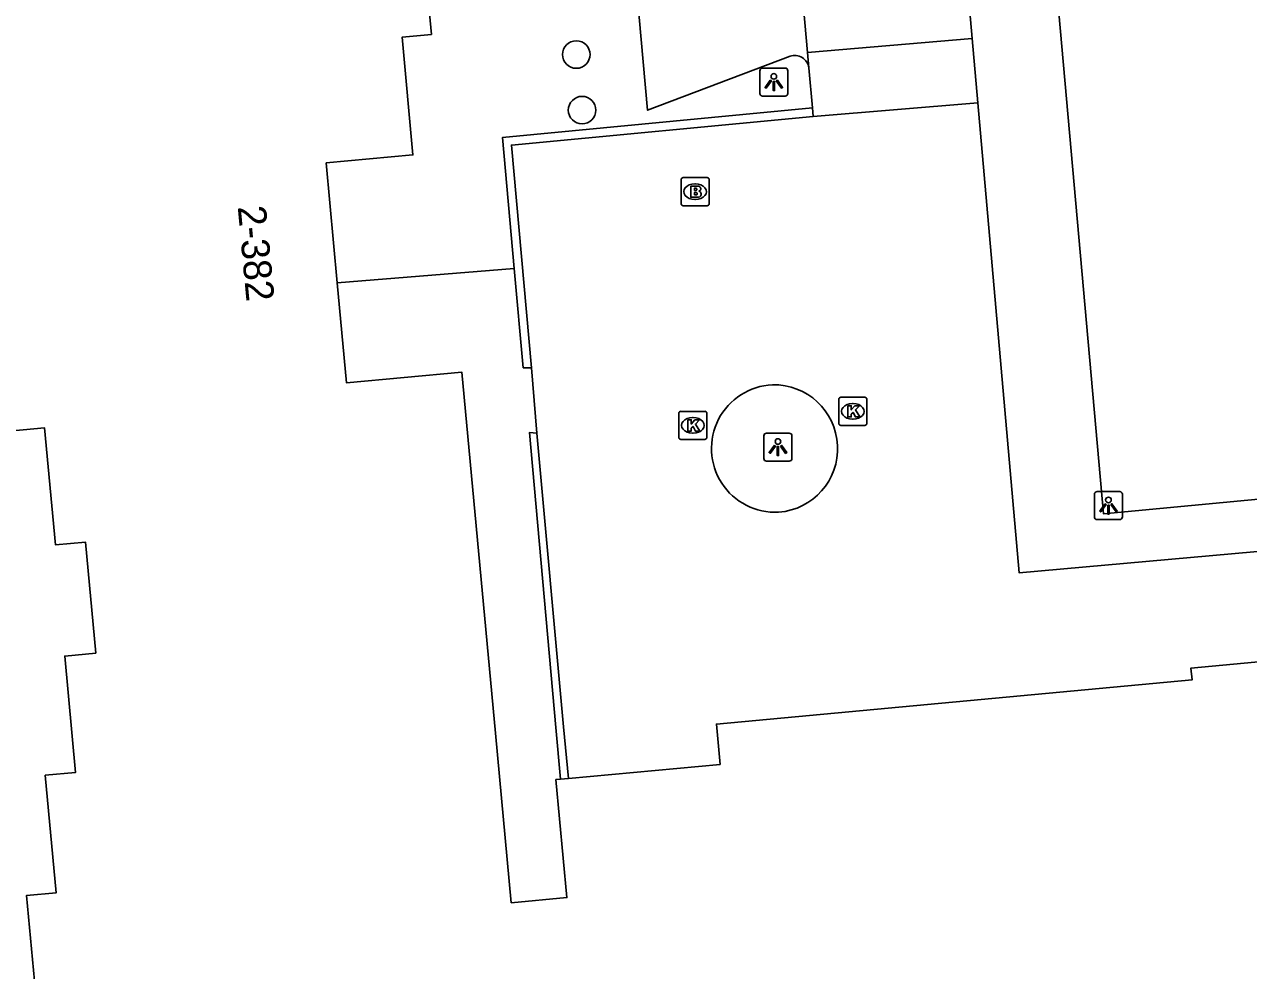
# Model space of a CAD drawing. Extents: x 157793 to 159380, y 380882 to 382313.
# Drawn here: x 158289.2 to 158332.75, y 381192.48 to 381226.15 of the extents above; entities that cross this region are included whole.
import ezdxf

# ---------------------------------------------------------------- set-up
doc = ezdxf.new("R2010")
doc.units = 0
for name, color, linetype in [('IMGEO_Boom', 7, 'Continuous'), ('IMGEO_Brandkraan', 7, 'Continuous'), ('IMGEO_Kolk', 7, 'Continuous'), ('IMGEO_Lichtpunt', 7, 'Continuous'), ('IMGEO_Muur', 7, 'Continuous'), ('IMGEO_Pand', 7, 'Continuous'), ('IMGEO_Pand_nummerreeks', 7, 'Continuous'), ('IMGEO_Parkeervlak_open', 7, 'Continuous'), ('IMGEO_Rijbaan_lokaal_open', 7, 'Continuous'), ('IMGEO_Voetpad_open', 7, 'Continuous')]:
    doc.layers.add(name, color=color, linetype=linetype)

msp = doc.modelspace()

# ---------------------------------------------------------------- linework, layer by layer
at = {"layer": 'IMGEO_Boom'}
for centre in [(158308.835, 381225.082), (158309.039, 381223.104)]:
    msp.add_circle(centre, 0.489, dxfattribs=at)
at = {"layer": 'IMGEO_Brandkraan'}
for p, q in [((158312.561, 381219.776), (158312.561, 381220.628)), ((158312.636, 381220.702), (158313.488, 381220.702)), ((158313.049, 381220.482), (158313.074, 381220.482)), ((158313.562, 381220.628), (158313.562, 381219.776)), ((158313.488, 381219.702), (158312.636, 381219.702)), ((158313.072, 381219.922), (158313.047, 381219.922))]:
    msp.add_line(p, q, dxfattribs=at)
for points in [[(158312.561, 381219.776), (158312.561, 381220.628)], [(158312.636, 381220.702), (158313.488, 381220.702)], [(158312.909, 381220.402), (158312.909, 381220.002), (158313.122, 381220.002)], [(158313.14, 381220.402), (158312.909, 381220.402)], [(158313.562, 381220.628), (158313.562, 381219.776)], [(158313.088, 381220.321), (158313.034, 381220.321), (158313.034, 381220.245)], [(158313.034, 381220.245), (158313.087, 381220.245)], [(158313.096, 381220.169), (158313.034, 381220.169), (158313.034, 381220.088)], [(158313.034, 381220.088), (158313.096, 381220.088)], [(158313.488, 381219.702), (158312.636, 381219.702)]]:
    msp.add_lwpolyline(points, dxfattribs=at)
for centre, radius, start, end in [((158312.638, 381220.626), 0.0765, 91.552, 178.448), ((158312.638, 381220.626), 0.0765, 91.552, 178.448), ((158313.144, 381220.257), 0.145, 59.4692, 91.5367), ((158313.486, 381220.626), 0.0765, 1.552, 88.448), ((158313.486, 381220.626), 0.0765, 1.552, 88.448), ((158313.089, 381220.283), 0.0379, 267.8285, 90.9355), ((158313.097, 381220.128), 0.0404, 269.8759, 90.5077), ((158313.128, 381220.253), 0.251, 268.6676, 293.5347), ((158313.169, 381220.304), 0.0922, 285.5137, 58.1501), ((158313.174, 381220.112), 0.105, 301.3115, 78.989), ((158312.638, 381219.778), 0.0765, 181.552, 268.448), ((158312.638, 381219.778), 0.0765, 181.552, 268.448), ((158313.486, 381219.778), 0.0765, 271.552, 358.448), ((158313.486, 381219.778), 0.0765, 271.552, 358.448)]:
    msp.add_arc(centre, radius, start, end, dxfattribs=at)
for centre, major_axis, ratio, start_param, end_param in [((158313.048, 381220.202), (-0.387, 0.002), 0.722429, 4.712389, 7.853982), ((158313.073, 381220.202), (-0.39, 0.002), 0.717154, 1.570796, 4.712389)]:
    msp.add_ellipse(centre, major_axis=major_axis, ratio=ratio, start_param=start_param, end_param=end_param, dxfattribs=at)
at = {"layer": 'IMGEO_Kolk'}
for p, q in [((158318.173, 381211.956), (158318.173, 381212.808)), ((158318.248, 381212.882), (158319.1, 381212.882)), ((158318.661, 381212.662), (158318.686, 381212.662)), ((158319.174, 381212.808), (158319.174, 381211.956)), ((158312.481, 381211.457), (158312.481, 381212.309)), ((158312.556, 381212.383), (158313.408, 381212.383)), ((158312.969, 381212.163), (158312.994, 381212.163)), ((158313.482, 381212.309), (158313.482, 381211.457)), ((158319.1, 381211.882), (158318.248, 381211.882)), ((158318.684, 381212.102), (158318.659, 381212.102)), ((158313.408, 381211.383), (158312.556, 381211.383)), ((158312.992, 381211.603), (158312.967, 381211.603))]:
    msp.add_line(p, q, dxfattribs=at)
for points in [[(158318.173, 381211.956), (158318.173, 381212.808)], [(158318.248, 381212.882), (158319.1, 381212.882)], [(158318.494, 381212.582), (158318.617, 381212.582), (158318.617, 381212.431), (158318.747, 381212.582), (158318.911, 381212.582), (158318.765, 381212.431), (158318.918, 381212.182), (158318.766, 381212.182), (158318.681, 381212.346), (158318.617, 381212.279), (158318.617, 381212.182), (158318.494, 381212.182), (158318.494, 381212.582)], [(158319.174, 381212.808), (158319.174, 381211.956)], [(158312.481, 381211.457), (158312.481, 381212.309)], [(158312.556, 381212.383), (158313.408, 381212.383)], [(158313.482, 381212.309), (158313.482, 381211.457)], [(158312.802, 381212.083), (158312.925, 381212.083), (158312.925, 381211.932), (158313.055, 381212.083), (158313.219, 381212.083), (158313.073, 381211.932), (158313.226, 381211.683), (158313.074, 381211.683), (158312.989, 381211.847), (158312.925, 381211.78), (158312.925, 381211.683), (158312.802, 381211.683), (158312.802, 381212.083)], [(158319.1, 381211.882), (158318.248, 381211.882)], [(158313.408, 381211.383), (158312.556, 381211.383)]]:
    msp.add_lwpolyline(points, dxfattribs=at)
for centre, start, end in [((158318.25, 381212.806), 91.552, 178.448), ((158318.25, 381212.806), 91.552, 178.448), ((158319.098, 381212.806), 1.552, 88.448), ((158319.098, 381212.806), 1.552, 88.448), ((158312.558, 381212.307), 91.552, 178.448), ((158312.558, 381212.307), 91.552, 178.448), ((158313.406, 381212.307), 1.552, 88.448), ((158313.406, 381212.307), 1.552, 88.448), ((158318.25, 381211.958), 181.552, 268.448), ((158318.25, 381211.958), 181.552, 268.448), ((158319.098, 381211.958), 271.552, 358.448), ((158319.098, 381211.958), 271.552, 358.448), ((158312.558, 381211.459), 181.552, 268.448), ((158312.558, 381211.459), 181.552, 268.448), ((158313.406, 381211.459), 271.552, 358.448), ((158313.406, 381211.459), 271.552, 358.448)]:
    msp.add_arc(centre, 0.0765, start, end, dxfattribs=at)
for centre, major_axis, ratio, start_param, end_param in [((158318.66, 381212.382), (-0.387, 0.002), 0.722429, 4.712389, 7.853982), ((158318.685, 381212.382), (-0.39, 0.002), 0.717154, 1.570796, 4.712389), ((158312.968, 381211.883), (-0.387, 0.002), 0.722429, 4.712389, 7.853982), ((158312.993, 381211.883), (-0.39, 0.002), 0.717154, 1.570796, 4.712389)]:
    msp.add_ellipse(centre, major_axis=major_axis, ratio=ratio, start_param=start_param, end_param=end_param, dxfattribs=at)
at = {"layer": 'IMGEO_Lichtpunt'}
for p, q in [((158315.364, 381224.507), (158315.364, 381223.7)), ((158315.364, 381224.507), (158315.364, 381223.7)), ((158316.266, 381224.602), (158315.458, 381224.602)), ((158316.266, 381224.602), (158315.458, 381224.602)), ((158316.36, 381223.7), (158316.36, 381224.507)), ((158316.36, 381223.7), (158316.36, 381224.507)), ((158315.458, 381223.606), (158316.266, 381223.606)), ((158315.458, 381223.606), (158316.266, 381223.606)), ((158315.509, 381211.513), (158315.509, 381210.706)), ((158315.509, 381211.513), (158315.509, 381210.706)), ((158316.411, 381211.608), (158315.603, 381211.608)), ((158316.411, 381211.608), (158315.603, 381211.608)), ((158316.505, 381210.706), (158316.505, 381211.513)), ((158316.505, 381210.706), (158316.505, 381211.513)), ((158315.603, 381210.612), (158316.411, 381210.612)), ((158315.603, 381210.612), (158316.411, 381210.612)), ((158328.172, 381209.527), (158327.364, 381209.527)), ((158328.172, 381209.527), (158327.364, 381209.527)), ((158327.27, 381209.432), (158327.27, 381208.625)), ((158327.27, 381209.432), (158327.27, 381208.625)), ((158328.266, 381208.625), (158328.266, 381209.432)), ((158328.266, 381208.625), (158328.266, 381209.432)), ((158327.364, 381208.531), (158328.172, 381208.531)), ((158327.364, 381208.531), (158328.172, 381208.531))]:
    msp.add_line(p, q, dxfattribs=at)
for points in [[(158315.738, 381224.171), (158315.777, 381224.143), (158315.589, 381223.881), (158315.551, 381223.908), (158315.738, 381224.171)], [(158315.84, 381224.123), (158315.887, 381224.123), (158315.887, 381223.801), (158315.84, 381223.801), (158315.84, 381224.123)], [(158315.95, 381224.143), (158315.988, 381224.17), (158316.175, 381223.908), (158316.136, 381223.88), (158315.95, 381224.143)], [(158315.883, 381211.177), (158315.922, 381211.149), (158315.734, 381210.887), (158315.696, 381210.914), (158315.883, 381211.177)], [(158315.985, 381211.129), (158316.032, 381211.129), (158316.032, 381210.807), (158315.985, 381210.807), (158315.985, 381211.129)], [(158316.095, 381211.149), (158316.133, 381211.176), (158316.32, 381210.914), (158316.281, 381210.886), (158316.095, 381211.149)], [(158327.644, 381209.096), (158327.683, 381209.068), (158327.495, 381208.806), (158327.457, 381208.833), (158327.644, 381209.096)], [(158327.856, 381209.068), (158327.894, 381209.095), (158328.081, 381208.833), (158328.042, 381208.805), (158327.856, 381209.068)], [(158327.746, 381209.048), (158327.793, 381209.048), (158327.793, 381208.726), (158327.746, 381208.726), (158327.746, 381209.048)]]:
    msp.add_lwpolyline(points, dxfattribs=at)
for centre in [(158315.863, 381224.305), (158316.008, 381211.311), (158327.769, 381209.23)]:
    msp.add_circle(centre, 0.0994, dxfattribs=at)
for centre, start, end in [((158315.458, 381224.507), 90, 180), ((158315.458, 381224.507), 90, 180), ((158316.266, 381224.507), 0, 90), ((158316.266, 381224.507), 0, 90), ((158315.458, 381223.7), 180, 270), ((158315.458, 381223.7), 180, 270), ((158316.266, 381223.7), 270, 0), ((158316.266, 381223.7), 270, 360), ((158315.603, 381211.513), 90, 180), ((158315.603, 381211.513), 90, 180), ((158316.411, 381211.513), 0, 90), ((158316.411, 381211.513), 0, 90), ((158315.603, 381210.706), 180, 270), ((158315.603, 381210.706), 180, 270), ((158316.411, 381210.706), 270, 0), ((158316.411, 381210.706), 270, 360), ((158327.364, 381209.432), 90, 180), ((158327.364, 381209.432), 90, 180), ((158328.172, 381209.432), 0, 90), ((158328.172, 381209.432), 0, 90), ((158327.364, 381208.625), 180, 270), ((158327.364, 381208.625), 180, 270), ((158328.172, 381208.625), 270, 0), ((158328.172, 381208.625), 270, 360)]:
    msp.add_arc(centre, 0.0946, start, end, dxfattribs=at)
at = {"layer": 'IMGEO_Muur'}
for points in [[(158306.627, 381217.472), (158306.209, 381222.134), (158317.24, 381223.185)], [(158317.24, 381223.185), (158317.267, 381222.88)], [(158317.267, 381222.88), (158306.525, 381221.862), (158307.24, 381213.936)], [(158307.24, 381213.936), (158306.944, 381213.934), (158306.627, 381217.472)], [(158308.266, 381199.289), (158308.101, 381201.134), (158307.165, 381211.625), (158307.427, 381211.606)], [(158307.427, 381211.606), (158308.383, 381201.16), (158308.552, 381199.315)]]:
    msp.add_lwpolyline(points, dxfattribs=at)
at = {"layer": 'IMGEO_Pand'}
for points in [[(158280.546, 381245.199), (158289.317, 381246.013), (158289.487, 381244.186), (158293.084, 381244.52), (158292.902, 381246.477), (158301.714, 381247.294), (158302.153, 381242.563), (158301.124, 381242.467), (158301.463, 381238.817), (158302.43, 381238.907), (158302.866, 381234.204), (158301.855, 381234.11), (158302.193, 381230.47), (158303.234, 381230.567), (158303.676, 381225.796), (158302.633, 381225.699), (158303.022, 381221.509), (158299.934, 381221.222), (158300.33, 381216.952)], [(158308.266, 381199.289), (158308.108, 381199.274), (158308.498, 381195.078), (158306.517, 381194.895), (158305.957, 381200.933), (158304.766, 381213.773), (158300.661, 381213.392), (158300.33, 381216.952)], [(158289.662, 381190.972), (158289.274, 381195.154), (158290.327, 381195.251), (158289.939, 381199.431), (158291.017, 381199.531), (158290.633, 381203.675), (158291.737, 381203.777), (158291.37, 381207.732), (158290.3, 381207.633), (158289.914, 381211.793), (158285.717, 381211.403)], [(158337.153, 381203.847), (158330.706, 381203.248), (158330.746, 381202.822), (158313.817, 381201.251), (158313.95, 381199.816), (158308.552, 381199.315)], [(158308.552, 381199.315), (158308.266, 381199.289)]]:
    msp.add_lwpolyline(points, dxfattribs=at)
at = {"layer": 'IMGEO_Parkeervlak_open'}
msp.add_lwpolyline([(158314.647, 381247.973), (158308.638, 381245.91), (158309.681, 381234.077), (158310.379, 381234.104), (158311.372, 381223.1), (158316.442, 381225.028)], dxfattribs=at)
msp.add_arc((158316.593, 381224.522), 0.528, 9.8903, 106.6378, dxfattribs=at)
at = {"layer": 'IMGEO_Rijbaan_lokaal_open'}
for points in [[(158322.923, 381225.654), (158320.788, 381250), (158320.437, 381255.089)], [(158317.065, 381225.153), (158316.305, 381233.712), (158315.245, 381246.182), (158315.091, 381248.608)], [(158317.065, 381225.153), (158322.923, 381225.654)], [(158323.124, 381223.369), (158322.923, 381225.654)], [(158317.113, 381224.613), (158317.065, 381225.153)], [(158317.24, 381223.185), (158317.113, 381224.613)], [(158323.124, 381223.369), (158317.267, 381222.88)], [(158337.153, 381203.847), (158336.78, 381207.73), (158324.591, 381206.639), (158323.124, 381223.369)], [(158307.427, 381211.606), (158307.24, 381213.936)]]:
    msp.add_lwpolyline(points, dxfattribs=at)
for centre, radius, start, end in [((158315.915, 381211.061), 2.27, 92.6522, 273.0046), ((158315.861, 381211.058), 2.271, 274.3651, 91.2916)]:
    msp.add_arc(centre, radius, start, end, dxfattribs=at)
at = {"layer": 'IMGEO_Voetpad_open'}
for points in [[(158323.432, 381255.431), (158323.916, 381250), (158327.593, 381208.735), (158343.248, 381210.224), (158342.684, 381216.132), (158344.186, 381216.287)], [(158300.33, 381216.952), (158306.627, 381217.472)]]:
    msp.add_lwpolyline(points, dxfattribs=at)

# ---------------------------------------------------------------- texts
at = {"layer": 'IMGEO_Pand_nummerreeks'}
msp.add_text('2-382', height=1, rotation=275.3046, dxfattribs=at).set_placement((158296.785, 381219.666))

doc.saveas('drawing.dxf')
